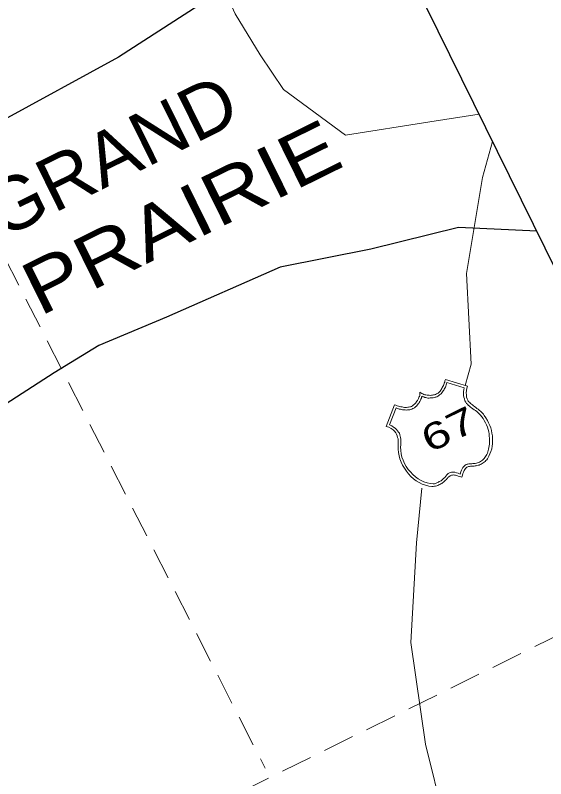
# Model space of a CAD drawing. Extents: x 2356606 to 2371222, y 6973096 to 6982644.
# Drawn here: x 2371051.8 to 2371153.5, y 6980347 to 6980493.4 of the extents above; entities that cross this region are included whole.
import ezdxf

# ---------------------------------------------------------------- set-up
doc = ezdxf.new("R2010")
doc.units = 0
doc.header["$LTSCALE"] = 2
doc.linetypes.add('MEDIUM_DASHED', pattern=[4.5, 3, -1.5])
doc.layers.add('62', color=7, linetype='Continuous', lineweight=13)
doc.layers.add('63', color=7, linetype='Continuous', lineweight=13)

msp = doc.modelspace()

# ---------------------------------------------------------------- linework, layer by layer
at = {"layer": '62', "linetype": 'MEDIUM_DASHED'}
for p, q in [((2370972, 6980599.301), (2371099.701, 6980348.989)), ((2370780.217, 6980189.078), (2371183.383, 6980388.055))]:
    msp.add_line(p, q, dxfattribs=at)
at = {"layer": '62'}
msp.add_line((2371139.26, 6980426.451), (2371138.083, 6980422.383), dxfattribs=at)
at = {"layer": '62', "lineweight": 25}
for points in [[(2370613.001, 6980527.892), (2370818.917, 6980110.665), (2371222.081, 6980309.64), (2371016.165, 6980726.869)], [(2371119.806, 6980516.871), (2371108.589, 6980509.904), (2371091.896, 6980498.532), (2371071.569, 6980485.363), (2371048.771, 6980472.932), (2371022.721, 6980460.075), (2370994.479, 6980445.157), (2370978.671, 6980436.103)], [(2371151.844, 6980451.959), (2371136.822, 6980452.699), (2371120.015, 6980448.521), (2371102.607, 6980445.048), (2371080.793, 6980435.46), (2371067.811, 6980430.032), (2371059.219, 6980424.813), (2371044.719, 6980415.501), (2371034.045, 6980410.232), (2371026.295, 6980405.753)]]:
    msp.add_lwpolyline(points, dxfattribs=at)
at = {"layer": '62'}
for points in [[(2371140.749, 6980474.436), (2371131.311, 6980472.965), (2371115.146, 6980470.385), (2371103.207, 6980479.12), (2371098.763, 6980485.784), (2371093.963, 6980493.63), (2371091.218, 6980499.802), (2371088.739, 6980506.958), (2371085.125, 6980512.653), (2371081.185, 6980520.999)], [(2371143.337, 6980469.187), (2371141.392, 6980462.257), (2371138.338, 6980443.887), (2371139.26, 6980426.451)], [(2371122.938, 6980414.531), (2371124.531, 6980418.678), (2371124.782, 6980418.577), (2371125.033, 6980418.474), (2371125.284, 6980418.423), (2371125.523, 6980418.341), (2371125.748, 6980418.3), (2371125.987, 6980418.268), (2371126.189, 6980418.216), (2371126.429, 6980418.185), (2371126.64, 6980418.165), (2371126.833, 6980418.184), (2371127.054, 6980418.193), (2371127.235, 6980418.233), (2371127.446, 6980418.262), (2371127.608, 6980418.29), (2371127.791, 6980418.381), (2371127.96, 6980418.492), (2371128.071, 6980418.568), (2371128.183, 6980418.699), (2371128.334, 6980418.8), (2371128.475, 6980418.92), (2371128.599, 6980419.08), (2371128.709, 6980419.21), (2371128.831, 6980419.37), (2371128.953, 6980419.53), (2371129.054, 6980419.731), (2371129.146, 6980419.901), (2371129.217, 6980420.115), (2371129.317, 6980420.265), (2371129.36, 6980420.486), (2371129.39, 6980420.676), (2371129.392, 6980420.878), (2371129.392, 6980421.08), (2371129.573, 6980420.967), (2371129.776, 6980420.867), (2371129.954, 6980420.754), (2371130.166, 6980420.683), (2371130.356, 6980420.601), (2371130.567, 6980420.578), (2371130.769, 6980420.527), (2371130.979, 6980420.507), (2371131.182, 6980420.504), (2371131.393, 6980420.484), (2371131.604, 6980420.512), (2371131.795, 6980420.532), (2371132.017, 6980420.593), (2371132.189, 6980420.6), (2371132.41, 6980420.66), (2371132.591, 6980420.749), (2371132.732, 6980420.819), (2371132.894, 6980420.899), (2371133.004, 6980421.028), (2371133.167, 6980421.159), (2371133.269, 6980421.309), (2371133.4, 6980421.451), (2371133.492, 6980421.62), (2371133.614, 6980421.781), (2371133.696, 6980421.972), (2371133.817, 6980422.182), (2371133.897, 6980422.372), (2371134.001, 6980422.574), (2371134.061, 6980422.804), (2371134.172, 6980423.036), (2371134.216, 6980423.259), (2371134.296, 6980423.498), (2371138.556, 6980422.237), (2371138.422, 6980421.849), (2371138.311, 6980421.416), (2371138.297, 6980420.983), (2371138.326, 6980420.57), (2371138.356, 6980420.158), (2371138.472, 6980419.814), (2371138.583, 6980419.543), (2371138.692, 6980419.369), (2371138.793, 6980419.218), (2371138.952, 6980419.098), (2371139.082, 6980418.935), (2371139.272, 6980418.802), (2371139.471, 6980418.652), (2371139.676, 6980418.5), (2371139.884, 6980418.327), (2371140.125, 6980418.146), (2371140.356, 6980417.985), (2371140.586, 6980417.821), (2371140.816, 6980417.609), (2371141.026, 6980417.436), (2371141.247, 6980417.242), (2371141.417, 6980417.051), (2371141.608, 6980416.871), (2371141.748, 6980416.638), (2371142.078, 6980416.173), (2371142.368, 6980415.688), (2371142.595, 6980415.223), (2371142.793, 6980414.72), (2371142.98, 6980414.237), (2371143.11, 6980413.723), (2371143.228, 6980413.228), (2371143.307, 6980412.714), (2371143.354, 6980412.212), (2371143.353, 6980411.709)], [(2371142.651, 6980410.484), (2371142.701, 6980410.785), (2371142.754, 6980411.139), (2371142.756, 6980411.49), (2371142.77, 6980411.874), (2371142.749, 6980412.265), (2371142.723, 6980412.678), (2371142.683, 6980413.112), (2371142.607, 6980413.524), (2371142.488, 6980413.967), (2371142.348, 6980414.4), (2371142.191, 6980414.823), (2371141.982, 6980415.247), (2371141.742, 6980415.682), (2371141.512, 6980416.046), (2371141.292, 6980416.388), (2371141.053, 6980416.671), (2371140.801, 6980416.924), (2371140.562, 6980417.156), (2371140.302, 6980417.38), (2371140.062, 6980417.563), (2371139.8, 6980417.733), (2371139.54, 6980417.907), (2371139.329, 6980418.078), (2371139.099, 6980418.241), (2371138.889, 6980418.413), (2371138.68, 6980418.584), (2371138.508, 6980418.779), (2371138.348, 6980418.949), (2371138.187, 6980419.171), (2371138.047, 6980419.454), (2371137.928, 6980419.795), (2371137.841, 6980420.13), (2371137.771, 6980420.47), (2371137.744, 6980420.833), (2371137.785, 6980421.205), (2371137.838, 6980421.559), (2371137.908, 6980421.919), (2371134.555, 6980422.923), (2371134.483, 6980422.714), (2371134.432, 6980422.51), (2371134.371, 6980422.279), (2371134.291, 6980422.09), (2371134.188, 6980421.888), (2371134.085, 6980421.689), (2371133.976, 6980421.508), (2371133.862, 6980421.328), (2371133.721, 6980421.158), (2371133.609, 6980420.977), (2371133.466, 6980420.806), (2371133.346, 6980420.696), (2371133.185, 6980420.567), (2371133.053, 6980420.476), (2371132.951, 6980420.376), (2371132.81, 6980420.305), (2371132.669, 6980420.235), (2371132.477, 6980420.167), (2371132.307, 6980420.109), (2371132.134, 6980420.049), (2371131.921, 6980420.018), (2371131.751, 6980420.009), (2371131.54, 6980419.981), (2371131.339, 6980419.982), (2371131.167, 6980419.973), (2371130.917, 6980419.974), (2371130.745, 6980420.015), (2371130.555, 6980420.047), (2371130.335, 6980420.087), (2371130.163, 6980420.178), (2371129.963, 6980420.231), (2371129.753, 6980420.353), (2371129.711, 6980420.132), (2371129.68, 6980419.94), (2371129.598, 6980419.75), (2371129.526, 6980419.589), (2371129.454, 6980419.427), (2371129.374, 6980419.287), (2371129.263, 6980419.108), (2371129.213, 6980418.957), (2371129.069, 6980418.838), (2371128.969, 6980418.688), (2371128.846, 6980418.575), (2371128.736, 6980418.446), (2371128.604, 6980418.356), (2371128.473, 6980418.216), (2371128.343, 6980418.126), (2371128.21, 6980418.034), (2371128.057, 6980417.937), (2371127.857, 6980417.837), (2371127.677, 6980417.798), (2371127.453, 6980417.738), (2371127.242, 6980417.709), (2371126.999, 6980417.69), (2371126.76, 6980417.672), (2371126.567, 6980417.703), (2371126.317, 6980417.702), (2371126.086, 6980417.714), (2371125.865, 6980417.756), (2371125.653, 6980417.828), (2371125.412, 6980417.86), (2371125.191, 6980417.951)], [(2371124.822, 6980418.094), (2371123.564, 6980414.84), (2371123.995, 6980414.627), (2371124.335, 6980414.393), (2371124.646, 6980414.17), (2371124.908, 6980413.948), (2371125.118, 6980413.675), (2371125.307, 6980413.441), (2371125.467, 6980413.22), (2371125.558, 6980412.937), (2371125.626, 6980412.646), (2371125.705, 6980412.382), (2371125.753, 6980412.08), (2371125.75, 6980411.78), (2371125.761, 6980411.509), (2371125.76, 6980411.204), (2371125.726, 6980410.916), (2371125.706, 6980410.603), (2371125.711, 6980409.928), (2371125.809, 6980409.273), (2371125.936, 6980408.66), (2371126.164, 6980408.044), (2371126.444, 6980407.427), (2371126.761, 6980406.833), (2371127.151, 6980406.297), (2371127.572, 6980405.802), (2371128.042, 6980405.305), (2371128.552, 6980404.881), (2371129.075, 6980404.486), (2371129.636, 6980404.163), (2371130.18, 6980403.929), (2371130.771, 6980403.693), (2371131.354, 6980403.58), (2371131.938, 6980403.517), (2371132.048, 6980403.547), (2371132.18, 6980403.536), (2371132.341, 6980403.564), (2371132.503, 6980403.645), (2371132.623, 6980403.705), (2371132.797, 6980403.765), (2371132.956, 6980403.843), (2371133.108, 6980403.943), (2371133.289, 6980404.033), (2371133.451, 6980404.112), (2371133.582, 6980404.252), (2371133.733, 6980404.353), (2371133.885, 6980404.453), (2371133.997, 6980404.583), (2371134.118, 6980404.693), (2371134.219, 6980404.793), (2371134.321, 6980404.943), (2371134.411, 6980405.063), (2371134.503, 6980405.184), (2371134.603, 6980405.283), (2371134.735, 6980405.423), (2371134.827, 6980405.494), (2371134.957, 6980405.584), (2371135.098, 6980405.654), (2371135.252, 6980405.704), (2371135.471, 6980405.762), (2371135.643, 6980405.77), (2371135.865, 6980405.732), (2371136.116, 6980405.729), (2371136.418, 6980405.628), (2371136.758, 6980405.545), (2371137.11, 6980405.392), (2371137.253, 6980405.812), (2371137.397, 6980406.135), (2371137.51, 6980406.416), (2371137.661, 6980406.667), (2371137.824, 6980406.848), (2371137.953, 6980406.987), (2371138.115, 6980407.116), (2371138.297, 6980407.207), (2371138.469, 6980407.266), (2371138.62, 6980407.317), (2371138.81, 6980407.334), (2371139.003, 6980407.355), (2371139.192, 6980407.374), (2371139.374, 6980407.361), (2371139.585, 6980407.391), (2371139.808, 6980407.401), (2371140.009, 6980407.45), (2371140.23, 6980407.459), (2371140.432, 6980407.559), (2371140.624, 6980407.627), (2371140.835, 6980407.705), (2371141.027, 6980407.827), (2371141.198, 6980407.937), (2371141.391, 6980408.055), (2371141.54, 6980408.207), (2371141.725, 6980408.347), (2371141.847, 6980408.557), (2371142.008, 6980408.736), (2371142.112, 6980408.937), (2371142.252, 6980409.158), (2371142.353, 6980409.41), (2371142.455, 6980409.661), (2371142.515, 6980409.891), (2371142.569, 6980410.193), (2371142.651, 6980410.484)], [(2371125.191, 6980417.951), (2371125, 6980418.031), (2371124.822, 6980418.094)], [(2371123.861, 6980414.134), (2371123.45, 6980414.356), (2371122.938, 6980414.531)], [(2371143.353, 6980411.709), (2371143.317, 6980411.216), (2371143.255, 6980410.733), (2371143.175, 6980410.24), (2371143.02, 6980409.739), (2371142.845, 6980409.277), (2371142.652, 6980408.805), (2371142.519, 6980408.563), (2371142.379, 6980408.342), (2371142.225, 6980408.142), (2371142.053, 6980407.984), (2371141.913, 6980407.813), (2371141.731, 6980407.671), (2371141.528, 6980407.521), (2371141.359, 6980407.412), (2371141.166, 6980407.292), (2371140.953, 6980407.213), (2371140.773, 6980407.125), (2371140.572, 6980407.073), (2371140.34, 6980407.037), (2371140.167, 6980406.976), (2371139.977, 6980406.958), (2371139.785, 6980406.937), (2371139.593, 6980406.918), (2371139.421, 6980406.909), (2371139.241, 6980406.923), (2371139.079, 6980406.889), (2371138.918, 6980406.862), (2371138.737, 6980406.822), (2371138.586, 6980406.771), (2371138.425, 6980406.692), (2371138.283, 6980406.572), (2371138.151, 6980406.432), (2371138.02, 6980406.242), (2371137.908, 6980406.062), (2371137.766, 6980405.789), (2371137.643, 6980405.532), (2371137.562, 6980405.186), (2371137.429, 6980404.795), (2371137.087, 6980404.928), (2371136.767, 6980405.021), (2371136.485, 6980405.135), (2371136.244, 6980405.164), (2371136.023, 6980405.205), (2371135.811, 6980405.228), (2371135.65, 6980405.197), (2371135.48, 6980405.189), (2371135.346, 6980405.148), (2371135.206, 6980405.079), (2371135.114, 6980405.008), (2371134.993, 6980404.9), (2371134.883, 6980404.82), (2371134.781, 6980404.719), (2371134.671, 6980404.589), (2371134.549, 6980404.48), (2371134.48, 6980404.368), (2371134.337, 6980404.249), (2371134.207, 6980404.108), (2371134.074, 6980403.969), (2371133.902, 6980403.857), (2371133.762, 6980403.738), (2371133.579, 6980403.6), (2371133.427, 6980403.499), (2371133.225, 6980403.399), (2371133.063, 6980403.32), (2371132.863, 6980403.22), (2371132.63, 6980403.131), (2371132.419, 6980403.102), (2371132.197, 6980403.042), (2371131.957, 6980403.022), (2371131.703, 6980403.026), (2371131.091, 6980403.099), (2371130.455, 6980403.262), (2371129.844, 6980403.485), (2371129.252, 6980403.77), (2371128.68, 6980404.117), (2371128.17, 6980404.491), (2371127.688, 6980404.956), (2371127.218, 6980405.453), (2371126.817, 6980405.958), (2371126.426, 6980406.493), (2371126.09, 6980407.078), (2371125.801, 6980407.664), (2371125.562, 6980408.297), (2371125.394, 6980408.894), (2371125.278, 6980409.537), (2371125.219, 6980410.162), (2371125.199, 6980410.401), (2371125.201, 6980410.655), (2371125.213, 6980410.937), (2371125.245, 6980411.229), (2371125.227, 6980411.519), (2371125.228, 6980411.821), (2371125.222, 6980412.144), (2371125.13, 6980412.425), (2371125.051, 6980412.739), (2371124.902, 6980413.041), (2371124.763, 6980413.324), (2371124.503, 6980413.597), (2371124.241, 6980413.87), (2371123.861, 6980414.134)], [(2371129.79, 6980402.682), (2371128.751, 6980392.231), (2371127.643, 6980373.115), (2371130.492, 6980353.618), (2371134.01, 6980339.372), (2371124.844, 6980320.22), (2371129.173, 6980311.136), (2371118.688, 6980295.474), (2371110.787, 6980281.739), (2371099.577, 6980268.15), (2371081.351, 6980254.436), (2371066.173, 6980242.076), (2371049.917, 6980228.034), (2371040.012, 6980219.782)]]:
    msp.add_lwpolyline(points, dxfattribs=at)
at = {"layer": '63', "linetype": 'MEDIUM_DASHED'}
for p, q in [((2370972, 6980599.301), (2371099.701, 6980348.989)), ((2370780.217, 6980189.078), (2371183.383, 6980388.055))]:
    msp.add_line(p, q, dxfattribs=at)
at = {"layer": '63'}
msp.add_line((2371139.26, 6980426.451), (2371138.083, 6980422.383), dxfattribs=at)
at = {"layer": '63', "lineweight": 25}
for points in [[(2370613.001, 6980527.892), (2370818.917, 6980110.665), (2371222.081, 6980309.64), (2371016.165, 6980726.869)], [(2371119.806, 6980516.871), (2371108.589, 6980509.904), (2371091.896, 6980498.532), (2371071.569, 6980485.363), (2371048.771, 6980472.932), (2371022.721, 6980460.075), (2370994.479, 6980445.157), (2370978.671, 6980436.103)], [(2371151.844, 6980451.959), (2371136.822, 6980452.699), (2371120.015, 6980448.521), (2371102.607, 6980445.048), (2371080.793, 6980435.46), (2371067.811, 6980430.032), (2371059.219, 6980424.813), (2371044.719, 6980415.501), (2371034.045, 6980410.232), (2371026.295, 6980405.753)]]:
    msp.add_lwpolyline(points, dxfattribs=at)
at = {"layer": '63'}
for points in [[(2371140.749, 6980474.436), (2371131.311, 6980472.965), (2371115.146, 6980470.385), (2371103.207, 6980479.12), (2371098.763, 6980485.784), (2371093.963, 6980493.63), (2371091.218, 6980499.802), (2371088.739, 6980506.958), (2371085.125, 6980512.653), (2371081.185, 6980520.999)], [(2371143.337, 6980469.187), (2371141.392, 6980462.257), (2371138.338, 6980443.887), (2371139.26, 6980426.451)], [(2371122.938, 6980414.531), (2371124.531, 6980418.678), (2371124.782, 6980418.577), (2371125.033, 6980418.474), (2371125.284, 6980418.423), (2371125.523, 6980418.341), (2371125.748, 6980418.3), (2371125.987, 6980418.268), (2371126.189, 6980418.216), (2371126.429, 6980418.185), (2371126.64, 6980418.165), (2371126.833, 6980418.184), (2371127.054, 6980418.193), (2371127.235, 6980418.233), (2371127.446, 6980418.262), (2371127.608, 6980418.29), (2371127.791, 6980418.381), (2371127.96, 6980418.492), (2371128.071, 6980418.568), (2371128.183, 6980418.699), (2371128.334, 6980418.8), (2371128.475, 6980418.92), (2371128.599, 6980419.08), (2371128.709, 6980419.21), (2371128.831, 6980419.37), (2371128.953, 6980419.53), (2371129.054, 6980419.731), (2371129.146, 6980419.901), (2371129.217, 6980420.115), (2371129.317, 6980420.265), (2371129.36, 6980420.486), (2371129.39, 6980420.676), (2371129.392, 6980420.878), (2371129.392, 6980421.08), (2371129.573, 6980420.967), (2371129.776, 6980420.867), (2371129.954, 6980420.754), (2371130.166, 6980420.683), (2371130.356, 6980420.601), (2371130.567, 6980420.578), (2371130.769, 6980420.527), (2371130.979, 6980420.507), (2371131.182, 6980420.504), (2371131.393, 6980420.484), (2371131.604, 6980420.512), (2371131.795, 6980420.532), (2371132.017, 6980420.593), (2371132.189, 6980420.6), (2371132.41, 6980420.66), (2371132.591, 6980420.749), (2371132.732, 6980420.819), (2371132.894, 6980420.899), (2371133.004, 6980421.028), (2371133.167, 6980421.159), (2371133.269, 6980421.309), (2371133.4, 6980421.451), (2371133.492, 6980421.62), (2371133.614, 6980421.781), (2371133.696, 6980421.972), (2371133.817, 6980422.182), (2371133.897, 6980422.372), (2371134.001, 6980422.574), (2371134.061, 6980422.804), (2371134.172, 6980423.036), (2371134.216, 6980423.259), (2371134.296, 6980423.498), (2371138.556, 6980422.237), (2371138.422, 6980421.849), (2371138.311, 6980421.416), (2371138.297, 6980420.983), (2371138.326, 6980420.57), (2371138.356, 6980420.158), (2371138.472, 6980419.814), (2371138.583, 6980419.543), (2371138.692, 6980419.369), (2371138.793, 6980419.218), (2371138.952, 6980419.098), (2371139.082, 6980418.935), (2371139.272, 6980418.802), (2371139.471, 6980418.652), (2371139.676, 6980418.5), (2371139.884, 6980418.327), (2371140.125, 6980418.146), (2371140.356, 6980417.985), (2371140.586, 6980417.821), (2371140.816, 6980417.609), (2371141.026, 6980417.436), (2371141.247, 6980417.242), (2371141.417, 6980417.051), (2371141.608, 6980416.871), (2371141.748, 6980416.638), (2371142.078, 6980416.173), (2371142.368, 6980415.688), (2371142.595, 6980415.223), (2371142.793, 6980414.72), (2371142.98, 6980414.237), (2371143.11, 6980413.723), (2371143.228, 6980413.228), (2371143.307, 6980412.714), (2371143.354, 6980412.212), (2371143.353, 6980411.709)], [(2371142.651, 6980410.484), (2371142.701, 6980410.785), (2371142.754, 6980411.139), (2371142.756, 6980411.49), (2371142.77, 6980411.874), (2371142.749, 6980412.265), (2371142.723, 6980412.678), (2371142.683, 6980413.112), (2371142.607, 6980413.524), (2371142.488, 6980413.967), (2371142.348, 6980414.4), (2371142.191, 6980414.823), (2371141.982, 6980415.247), (2371141.742, 6980415.682), (2371141.512, 6980416.046), (2371141.292, 6980416.388), (2371141.053, 6980416.671), (2371140.801, 6980416.924), (2371140.562, 6980417.156), (2371140.302, 6980417.38), (2371140.062, 6980417.563), (2371139.8, 6980417.733), (2371139.54, 6980417.907), (2371139.329, 6980418.078), (2371139.099, 6980418.241), (2371138.889, 6980418.413), (2371138.68, 6980418.584), (2371138.508, 6980418.779), (2371138.348, 6980418.949), (2371138.187, 6980419.171), (2371138.047, 6980419.454), (2371137.928, 6980419.795), (2371137.841, 6980420.13), (2371137.771, 6980420.47), (2371137.744, 6980420.833), (2371137.785, 6980421.205), (2371137.838, 6980421.559), (2371137.908, 6980421.919), (2371134.555, 6980422.923), (2371134.483, 6980422.714), (2371134.432, 6980422.51), (2371134.371, 6980422.279), (2371134.291, 6980422.09), (2371134.188, 6980421.888), (2371134.085, 6980421.689), (2371133.976, 6980421.508), (2371133.862, 6980421.328), (2371133.721, 6980421.158), (2371133.609, 6980420.977), (2371133.466, 6980420.806), (2371133.346, 6980420.696), (2371133.185, 6980420.567), (2371133.053, 6980420.476), (2371132.951, 6980420.376), (2371132.81, 6980420.305), (2371132.669, 6980420.235), (2371132.477, 6980420.167), (2371132.307, 6980420.109), (2371132.134, 6980420.049), (2371131.921, 6980420.018), (2371131.751, 6980420.009), (2371131.54, 6980419.981), (2371131.339, 6980419.982), (2371131.167, 6980419.973), (2371130.917, 6980419.974), (2371130.745, 6980420.015), (2371130.555, 6980420.047), (2371130.335, 6980420.087), (2371130.163, 6980420.178), (2371129.963, 6980420.231), (2371129.753, 6980420.353), (2371129.711, 6980420.132), (2371129.68, 6980419.94), (2371129.598, 6980419.75), (2371129.526, 6980419.589), (2371129.454, 6980419.427), (2371129.374, 6980419.287), (2371129.263, 6980419.108), (2371129.213, 6980418.957), (2371129.069, 6980418.838), (2371128.969, 6980418.688), (2371128.846, 6980418.575), (2371128.736, 6980418.446), (2371128.604, 6980418.356), (2371128.473, 6980418.216), (2371128.343, 6980418.126), (2371128.21, 6980418.034), (2371128.057, 6980417.937), (2371127.857, 6980417.837), (2371127.677, 6980417.798), (2371127.453, 6980417.738), (2371127.242, 6980417.709), (2371126.999, 6980417.69), (2371126.76, 6980417.672), (2371126.567, 6980417.703), (2371126.317, 6980417.702), (2371126.086, 6980417.714), (2371125.865, 6980417.756), (2371125.653, 6980417.828), (2371125.412, 6980417.86), (2371125.191, 6980417.951)], [(2371124.822, 6980418.094), (2371123.564, 6980414.84), (2371123.995, 6980414.627), (2371124.335, 6980414.393), (2371124.646, 6980414.17), (2371124.908, 6980413.948), (2371125.118, 6980413.675), (2371125.307, 6980413.441), (2371125.467, 6980413.22), (2371125.558, 6980412.937), (2371125.626, 6980412.646), (2371125.705, 6980412.382), (2371125.753, 6980412.08), (2371125.75, 6980411.78), (2371125.761, 6980411.509), (2371125.76, 6980411.204), (2371125.726, 6980410.916), (2371125.706, 6980410.603), (2371125.711, 6980409.928), (2371125.809, 6980409.273), (2371125.936, 6980408.66), (2371126.164, 6980408.044), (2371126.444, 6980407.427), (2371126.761, 6980406.833), (2371127.151, 6980406.297), (2371127.572, 6980405.802), (2371128.042, 6980405.305), (2371128.552, 6980404.881), (2371129.075, 6980404.486), (2371129.636, 6980404.163), (2371130.18, 6980403.929), (2371130.771, 6980403.693), (2371131.354, 6980403.58), (2371131.938, 6980403.517), (2371132.048, 6980403.547), (2371132.18, 6980403.536), (2371132.341, 6980403.564), (2371132.503, 6980403.645), (2371132.623, 6980403.705), (2371132.797, 6980403.765), (2371132.956, 6980403.843), (2371133.108, 6980403.943), (2371133.289, 6980404.033), (2371133.451, 6980404.112), (2371133.582, 6980404.252), (2371133.733, 6980404.353), (2371133.885, 6980404.453), (2371133.997, 6980404.583), (2371134.118, 6980404.693), (2371134.219, 6980404.793), (2371134.321, 6980404.943), (2371134.411, 6980405.063), (2371134.503, 6980405.184), (2371134.603, 6980405.283), (2371134.735, 6980405.423), (2371134.827, 6980405.494), (2371134.957, 6980405.584), (2371135.098, 6980405.654), (2371135.252, 6980405.704), (2371135.471, 6980405.762), (2371135.643, 6980405.77), (2371135.865, 6980405.732), (2371136.116, 6980405.729), (2371136.418, 6980405.628), (2371136.758, 6980405.545), (2371137.11, 6980405.392), (2371137.253, 6980405.812), (2371137.397, 6980406.135), (2371137.51, 6980406.416), (2371137.661, 6980406.667), (2371137.824, 6980406.848), (2371137.953, 6980406.987), (2371138.115, 6980407.116), (2371138.297, 6980407.207), (2371138.469, 6980407.266), (2371138.62, 6980407.317), (2371138.81, 6980407.334), (2371139.003, 6980407.355), (2371139.192, 6980407.374), (2371139.374, 6980407.361), (2371139.585, 6980407.391), (2371139.808, 6980407.401), (2371140.009, 6980407.45), (2371140.23, 6980407.459), (2371140.432, 6980407.559), (2371140.624, 6980407.627), (2371140.835, 6980407.705), (2371141.027, 6980407.827), (2371141.198, 6980407.937), (2371141.391, 6980408.055), (2371141.54, 6980408.207), (2371141.725, 6980408.347), (2371141.847, 6980408.557), (2371142.008, 6980408.736), (2371142.112, 6980408.937), (2371142.252, 6980409.158), (2371142.353, 6980409.41), (2371142.455, 6980409.661), (2371142.515, 6980409.891), (2371142.569, 6980410.193), (2371142.651, 6980410.484)], [(2371125.191, 6980417.951), (2371125, 6980418.031), (2371124.822, 6980418.094)], [(2371123.861, 6980414.134), (2371123.45, 6980414.356), (2371122.938, 6980414.531)], [(2371143.353, 6980411.709), (2371143.317, 6980411.216), (2371143.255, 6980410.733), (2371143.175, 6980410.24), (2371143.02, 6980409.739), (2371142.845, 6980409.277), (2371142.652, 6980408.805), (2371142.519, 6980408.563), (2371142.379, 6980408.342), (2371142.225, 6980408.142), (2371142.053, 6980407.984), (2371141.913, 6980407.813), (2371141.731, 6980407.671), (2371141.528, 6980407.521), (2371141.359, 6980407.412), (2371141.166, 6980407.292), (2371140.953, 6980407.213), (2371140.773, 6980407.125), (2371140.572, 6980407.073), (2371140.34, 6980407.037), (2371140.167, 6980406.976), (2371139.977, 6980406.958), (2371139.785, 6980406.937), (2371139.593, 6980406.918), (2371139.421, 6980406.909), (2371139.241, 6980406.923), (2371139.079, 6980406.889), (2371138.918, 6980406.862), (2371138.737, 6980406.822), (2371138.586, 6980406.771), (2371138.425, 6980406.692), (2371138.283, 6980406.572), (2371138.151, 6980406.432), (2371138.02, 6980406.242), (2371137.908, 6980406.062), (2371137.766, 6980405.789), (2371137.643, 6980405.532), (2371137.562, 6980405.186), (2371137.429, 6980404.795), (2371137.087, 6980404.928), (2371136.767, 6980405.021), (2371136.485, 6980405.135), (2371136.244, 6980405.164), (2371136.023, 6980405.205), (2371135.811, 6980405.228), (2371135.65, 6980405.197), (2371135.48, 6980405.189), (2371135.346, 6980405.148), (2371135.206, 6980405.079), (2371135.114, 6980405.008), (2371134.993, 6980404.9), (2371134.883, 6980404.82), (2371134.781, 6980404.719), (2371134.671, 6980404.589), (2371134.549, 6980404.48), (2371134.48, 6980404.368), (2371134.337, 6980404.249), (2371134.207, 6980404.108), (2371134.074, 6980403.969), (2371133.902, 6980403.857), (2371133.762, 6980403.738), (2371133.579, 6980403.6), (2371133.427, 6980403.499), (2371133.225, 6980403.399), (2371133.063, 6980403.32), (2371132.863, 6980403.22), (2371132.63, 6980403.131), (2371132.419, 6980403.102), (2371132.197, 6980403.042), (2371131.957, 6980403.022), (2371131.703, 6980403.026), (2371131.091, 6980403.099), (2371130.455, 6980403.262), (2371129.844, 6980403.485), (2371129.252, 6980403.77), (2371128.68, 6980404.117), (2371128.17, 6980404.491), (2371127.688, 6980404.956), (2371127.218, 6980405.453), (2371126.817, 6980405.958), (2371126.426, 6980406.493), (2371126.09, 6980407.078), (2371125.801, 6980407.664), (2371125.562, 6980408.297), (2371125.394, 6980408.894), (2371125.278, 6980409.537), (2371125.219, 6980410.162), (2371125.199, 6980410.401), (2371125.201, 6980410.655), (2371125.213, 6980410.937), (2371125.245, 6980411.229), (2371125.227, 6980411.519), (2371125.228, 6980411.821), (2371125.222, 6980412.144), (2371125.13, 6980412.425), (2371125.051, 6980412.739), (2371124.902, 6980413.041), (2371124.763, 6980413.324), (2371124.503, 6980413.597), (2371124.241, 6980413.87), (2371123.861, 6980414.134)], [(2371129.79, 6980402.682), (2371128.751, 6980392.231), (2371127.643, 6980373.115), (2371130.492, 6980353.618), (2371134.01, 6980339.372), (2371124.844, 6980320.22), (2371129.173, 6980311.136), (2371118.688, 6980295.474), (2371110.787, 6980281.739), (2371099.577, 6980268.15), (2371081.351, 6980254.436), (2371066.173, 6980242.076), (2371049.917, 6980228.034), (2371040.012, 6980219.782)]]:
    msp.add_lwpolyline(points, dxfattribs=at)

# ---------------------------------------------------------------- texts
at = {"layer": '62'}
for s, height, width, p in [('GRAND', 10.21, 1.05, (2371049.119, 6980450.418)), ('PRAIRIE', 10.21, 1.2, (2371056.448, 6980435.568)), ('67', 5.099, 1.4, (2371131.264, 6980409.358))]:
    msp.add_text(s, height=height, rotation=26.268, dxfattribs=dict(at, width=width)).set_placement(p)
at = {"layer": '63'}
for s, height, width, p in [('GRAND', 10.21, 1.05, (2371049.119, 6980450.418)), ('PRAIRIE', 10.21, 1.2, (2371056.448, 6980435.568)), ('67', 5.099, 1.4, (2371131.264, 6980409.358))]:
    msp.add_text(s, height=height, rotation=26.268, dxfattribs=dict(at, width=width)).set_placement(p)

doc.saveas('drawing.dxf')
